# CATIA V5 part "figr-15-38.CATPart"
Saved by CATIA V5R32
Part number: Part1
Bounding box of the stored display mesh (mm): x -63.331 to 69.186, y -39.139 to 39.139, z 0 to 69.963
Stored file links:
  D:\PROJECTS\Project 2022\CATIA V5 6R 2022\Resources\Part Files\c15_catia_v5_6r2022_prt\figr-15-38.CATPart
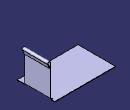
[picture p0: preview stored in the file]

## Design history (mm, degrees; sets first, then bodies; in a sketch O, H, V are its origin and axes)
SheetMetalParameters1: Thickness 1, BendRadius 2, KFactor 0.400515 {= log(min(100,max(20*SheetMetalParameters1.BendRadius,SheetMetalParameters1.Thickness)/SheetMetalParameters1.Thickness))/log(100)/2}, ReliefRadialLength 1, ReliefAxialLength 2, MinimumBendRadius 0
Body1 (main body)
  Sketch1 on xy-plane, origin (0, 0, 0), H (1, 0, 0), V (0, 1, 0)
    line L1 (-63.3311, 39.1393) -> (63.3311, 39.1393)
    line L2 (63.3311, 39.1393) -> (63.3311, -39.1393)
    line L3 (63.3311, -39.1393) -> (-63.3311, -39.1393)
    line L4 (-63.3311, -39.1393) -> (-63.3311, 39.1393)
    horizontal: L1 H, L3 H
    vertical: L2 V, L4 V
    symmetry: L4 L2 V, L1 L3 H
  Wall1: Thickness 1, Profile Sketch1
  d_NewWallOnEdge1: NewWallOnEdge_Edge edge [face of Wall1 | face of Wall1], NewWallOnEdge_Length 67, NewWallOnEdge_HeightLimitOffset 0, NewWallOnEdge_WidthOffset1 -16, NewWallOnEdge_WidthOffset2 -9, NewWallOnEdge_Angle 90, NewWallOnEdge_BendRadiusValue 2 {= SheetMetalParameters1.BendRadius}, NewWallOnEdge_BendTable SheetMetalParameters1, KFacteur 0.400515 {= log(min(100,max(20*d_NewWallOnEdge1.Radius,SheetMetalParameters1.Thickness)/SheetMetalParameters1.Thickness))/log(100)/2}
  Flange1: Angle 22.6199 {= 2*atan(Flange1.Radius/Flange1.Length)}, Length 10, Radius 2, KFacteur 0.400515 {= log(min(100,max(20*Flange1.Radius,SheetMetalParameters1.Thickness)/SheetMetalParameters1.Thickness))/log(100)/2}, Guide edge [face of d_NewWallOnEdge1 | face of d_NewWallOnEdge1]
